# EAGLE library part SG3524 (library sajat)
PULSE WIDTH MODULATOR
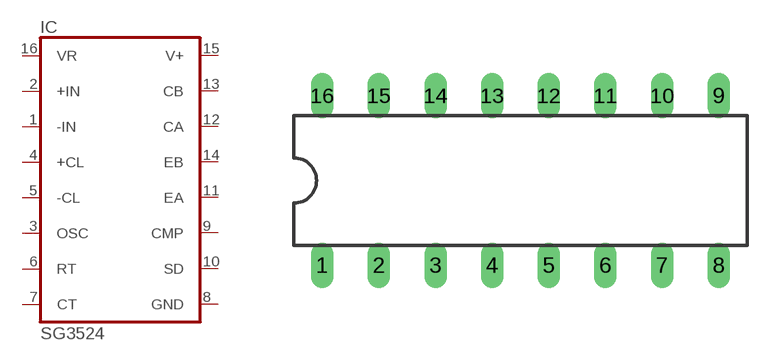
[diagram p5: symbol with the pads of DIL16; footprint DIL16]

Designator prefix IC

## SG3524LMN  [DIL16]
1  -IN  in
2  +IN  in
3  OSC  out
4  +CL  in
5  -CL  in
6  RT  pas
7  CT  pas
8  GND  pwr
9  CMP  pas
10  SD  in
11  EA
12  CA
13  CB
14  EB
15  V+  pwr
16  VR  out

## Footprint DIL16 (pad centres in mm)
Dual In Line Package
drill 0.3 pad 1.016 long: 1 -8.89,-3.81; 2 -6.35,-3.81; 3 -3.81,-3.81; 4 -1.27,-3.81; 5 1.27,-3.81; 6 3.81,-3.81; 7 6.35,-3.81; 8 8.89,-3.81; 9 8.89,3.81; 10 6.35,3.81; 11 3.81,3.81; 12 1.27,3.81; 13 -1.27,3.81; 14 -3.81,3.81; 15 -6.35,3.81; 16 -8.89,3.81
